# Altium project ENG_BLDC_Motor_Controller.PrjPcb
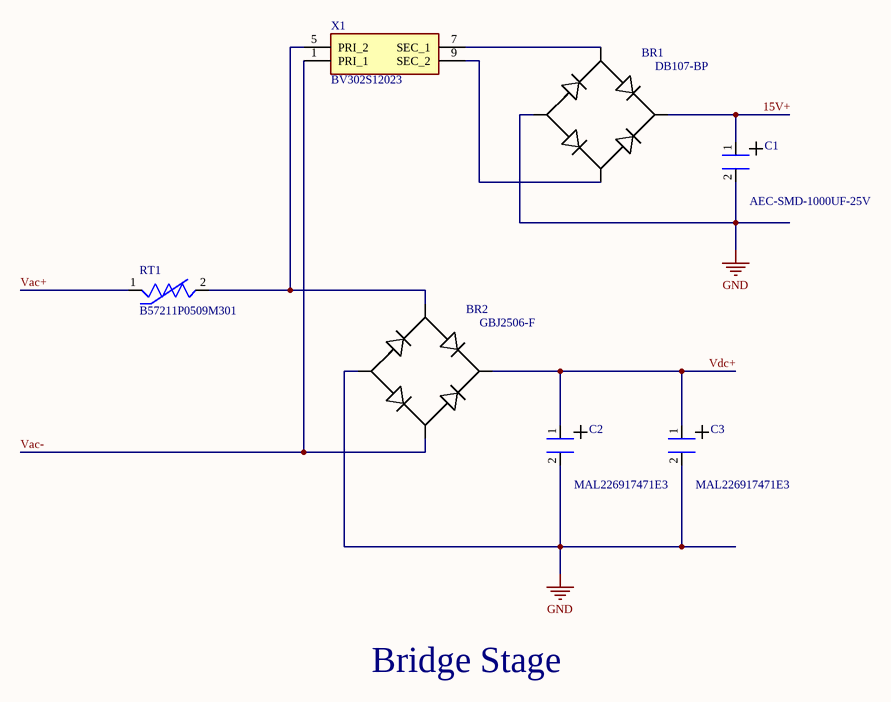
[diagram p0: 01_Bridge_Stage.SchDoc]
3 sheets, 49 parts. Net scope: global (net labels, ports and power ports of the same name join across sheets).
Board file: PCB_Main.PcbDoc
Sheets:
  01_Bridge_Stage.SchDoc
  02_MosfetDrive_Stage.SchDoc
  03_Headers-Mesaurements.SchDoc

## Sheet 01_Bridge_Stage.SchDoc
size A4; SheetNumber: 1; SheetTotal: 3

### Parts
BR1  DB107-BP  [898_DB107-BP]
BR2  GBJ2506-F  [996_GBJ2506-F]
C1  AEC-SMD-1000UF-25V  [098_AEC-SMD-1000UF-25V]
C2  MAL226917471E3  [099_MAL226917471E3]
C3  MAL226917471E3  [099_MAL226917471E3]
RT1  B57211P0509M301  [307_THRMRB750W80L1300T600H2000]
X1  BV302S12023  [899_BV302S12023]

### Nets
GND: BR1.2 BR2.4 C1.2 C2.2 C3.2
15V+: BR1.1 C1.1
Vac+: RT1.1
Vac-: BR2.3 X1.1(PRI_1)
Vdc+: BR2.1 C2.1 C3.1
NetBR1_3: BR1.3 X1.7(SEC_1)
NetBR1_4: BR1.4 X1.9(SEC_2)
NetBR2_2: BR2.2 RT1.2 X1.5(PRI_2)

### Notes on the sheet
- Bridge Stage

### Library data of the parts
BR1 = DB107-BP: Description; Manufacturer_Name: MCC
BR2 = GBJ2506-F: Bridge Rectifier; Manufacturer_Name: Diodes Incorporated
C1 = AEC-SMD-1000UF-25V: 1000 µF, 25 V polarized aluminum electrolytic capacitor, SMD V-chip package, Ø10 mm body, approx. 10.5 mm height, 105 °C rated.
C2 C3 = MAL226917471E3: 470 µF, 450 V polarized aluminum electrolytic capacitor, snap-in THT, Ø35 mm body, 10 mm lead spacing, 105 °C rated.
RT1 = B57211P0509M301: Inrush Current Limiter 5 Ohms Â±20% 5 A 0.512 (13.00mm); MF: EPCOS
X1 = BV302S12023: 2.3VA Encapsulated Transformer 50/60Hz; Manufacturer_Name: Zettler Group; Geometry.Height: 29.8mm

## Sheet 02_MosfetDrive_Stage.SchDoc
size A4; SheetNumber: 2; SheetTotal: 3
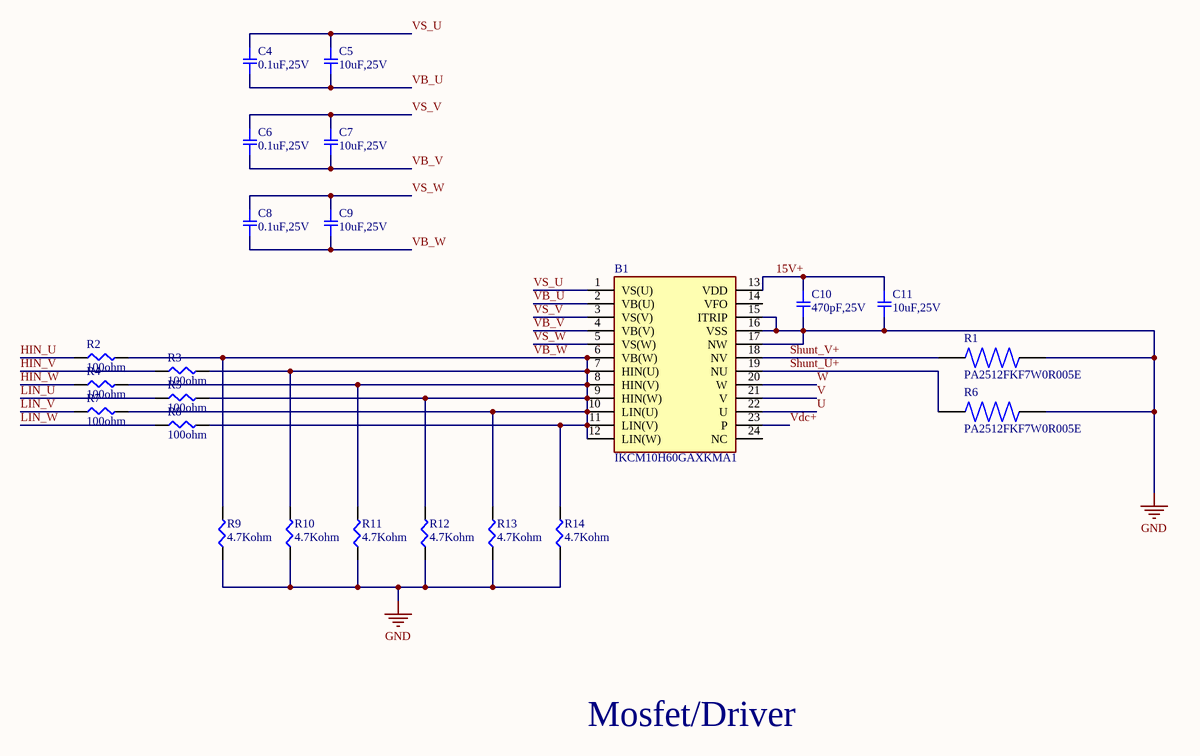
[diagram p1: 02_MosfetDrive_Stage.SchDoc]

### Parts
B1  IKCM10H60GAXKMA1  [997_IKCM10H60GAXKMA1]
C4  0.1uF,25V  [001_SMD-1206]
C5  10uF,25V  [001_SMD-1206]
C6  0.1uF,25V  [001_SMD-1206]
C7  10uF,25V  [001_SMD-1206]
C8  0.1uF,25V  [001_SMD-1206]
C9  10uF,25V  [001_SMD-1206]
C10  470pF,25V  [006_SMD_0605]
C11  10uF,25V  [006_SMD_0605]
R1  PA2512FKF7W0R005E  [097_PA2512FKF7W0R005E]
R2  100ohm  [001_SMD-1206]
R3  100ohm  [001_SMD-1206]
R4  100ohm  [001_SMD-1206]
R5  100ohm  [001_SMD-1206]
R6  PA2512FKF7W0R005E  [097_PA2512FKF7W0R005E]
R7  100ohm  [001_SMD-1206]
R8  100ohm  [001_SMD-1206]
R9  4.7Kohm  [001_SMD-1206]
R10  4.7Kohm  [001_SMD-1206]
R11  4.7Kohm  [001_SMD-1206]
R12  4.7Kohm  [001_SMD-1206]
R13  4.7Kohm  [001_SMD-1206]
R14  4.7Kohm  [001_SMD-1206]

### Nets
GND: B1.15(ITRIP) B1.16(VSS) B1.17(NW) C10.2 C11.2 R1.2 R6.2 R9.1 R10.1 R11.1 R12.1 R13.1 R14.1
15V+: B1.13(VDD) C10.1 C11.1
HIN_U: R2.1
HIN_V: R3.1
HIN_W: R4.1
LIN_U: R5.1
LIN_V: R7.1
LIN_W: R8.1
Shunt_U+: B1.19(NU) R6.1
Shunt_V+: B1.18(NV) R1.1
U: B1.22(U)
V: B1.21(V)
VB_U: B1.2(VB(U)) C4.2 C5.2
VB_V: B1.4(VB(V)) C6.2 C7.2
VB_W: B1.6(VB(W)) B1.7(HIN(U)) B1.8(HIN(V)) B1.9(HIN(W)) B1.10(LIN(U)) B1.11(LIN(V)) B1.12(LIN(W)) C8.2 C9.2 R2.2 R3.2 R4.2 R5.2 R7.2 R8.2 R9.2 R10.2 R11.2 R12.2 R13.2 R14.2
Vdc+: B1.23(P)
VS_U: B1.1(VS(U)) C4.1 C5.1
VS_V: B1.3(VS(V)) C6.1 C7.1
VS_W: B1.5(VS(W)) C8.1 C9.1
W: B1.20(W)

Not connected (* = marked no-connect by the designer): B1 14(VFO) 24(NC)

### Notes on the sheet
- Mosfet/Driver

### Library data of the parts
B1 = IKCM10H60GAXKMA1: Intelligent Power Module 3-Ph 600V 10A; Manufacturer_Name: Infineon; Geometry.Height: 5.6mm
C4-C9 = C_1206_Template: CAP CER 1206; Part Number: GC321AD72E103KX01D; Manufacturer: Murata Electronics North America; Factory Stock: 0; Unit Price (USD): 0.3; Minimum Quantity: 1; Value: 10000pF; Tolerance: ±10%; Voltage: 250V; Temperature Coefficient: X7T
C10 C11 = C_0605_Template: CAP CER 0605; Part Number: GC321AD72E103KX01D; Manufacturer: Murata Electronics North America; Factory Stock: 0; Unit Price (USD): 0.3; Minimum Quantity: 1; Value: 10000pF; Tolerance: ±10%; Voltage: 250V; Temperature Coefficient: X7T
R1 R6 = PA2512FKF7W0R005E: 5 mΩ, 2 W, ±1% current-sense shunt resistor, 2512 (6332 metric) SMD package, low-resistance metal-element construction.; MF: Bourns; MP: CRF2512-FZ-R005ELF
R2-R5 R7-R14 = R_1206_Template: RES SMD 1206; Part Number: ERJ-8BQF1R0V; Manufacturer: Panasonic Electronic Components; Factory Stock: 0; Unit Price (USD): 0.05778; @ qty: 1500; Minimum Quantity: 1; Value: 1; Tolerance: ±1%; Power (Watts): 0.5W, 1/2W; Temperature Coefficient: ±200ppm/°C

## Sheet 03_Headers-Mesaurements.SchDoc
size A4; SheetNumber: 3; SheetTotal: 3
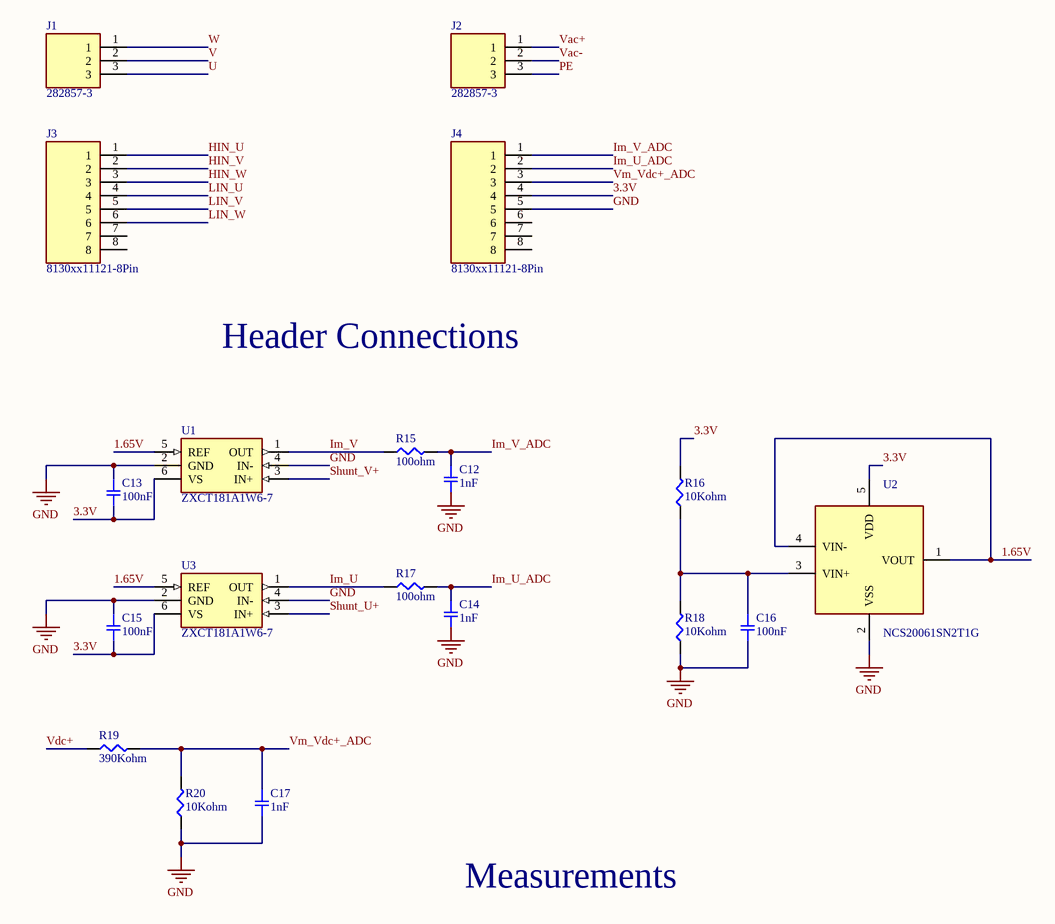
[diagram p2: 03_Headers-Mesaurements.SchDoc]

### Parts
C12  1nF  [006_SMD_0605]
C13  100nF  [006_SMD_0605]
C14  1nF  [006_SMD_0605]
C15  100nF  [006_SMD_0605]
C16  100nF  [001_SMD-1206]
C17  1nF  [006_SMD_0605]
J1  282857-3  [201_TE_282857-3]
J2  282857-3  [201_TE_282857-3]
J3  8130xx11121-8Pin  [200_HDRV6W64P0X254_1X6_1524X254X869P]
J4  8130xx11121-8Pin  [200_HDRV6W64P0X254_1X6_1524X254X869P]
R15  100ohm  [006_SMD_0605]
R16  10Kohm  [001_SMD-1206]
R17  100ohm  [006_SMD_0605]
R18  10Kohm  [001_SMD-1206]
R19  390Kohm  [001_SMD-1206]
R20  10Kohm  [001_SMD-1206]
U1  ZXCT181A1W6-7  [896_ZXCT181A1W6-7]
U2  NCS20061SN2T1G  [897_NCS20061SN2T1G]
U3  ZXCT181A1W6-7  [896_ZXCT181A1W6-7]

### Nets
GND: C12.2 C13.1 C14.2 C15.1 C16.2 C17.2 J4.5 R18.1 R20.1 U1.2(GND) U1.4(IN-) U2.2(VSS) U3.2(GND) U3.4(IN-)
1.65V: U1.5(REF) U2.1(VOUT) U2.4(VIN-) U3.5(REF)
3.3V: C13.2 C15.2 J4.4 R16.2 U1.6(VS) U2.5(VDD) U3.6(VS)
HIN_U: J3.1
HIN_V: J3.2
HIN_W: J3.3
Im_U: R17.1 U3.1(OUT)
Im_U_ADC: C14.1 J4.2 R17.2
Im_V: R15.1 U1.1(OUT)
Im_V_ADC: C12.1 J4.1 R15.2
LIN_U: J3.4
LIN_V: J3.5
LIN_W: J3.6
PE: J2.3
Shunt_U+: U3.3(IN+)
Shunt_V+: U1.3(IN+)
U: J1.3
V: J1.2
Vac+: J2.1
Vac-: J2.2
Vdc+: R19.1
Vm_Vdc+_ADC: C17.1 J4.3 R19.2 R20.2
W: J1.1
NetC16_1: C16.1 R16.1 R18.2 U2.3(VIN+)

Not connected (* = marked no-connect by the designer): J3 7 8; J4 6 7 8

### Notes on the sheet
- Header Connections
- Measurements

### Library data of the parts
C12-C15 C17 = C_0605_Template: as C10 on sheet 02_MosfetDrive_Stage
C16 = C_1206_Template: as C4 on sheet 02_MosfetDrive_Stage
J1 J2 = 282857-3: 3 Position Wire to Board Terminal Block Horizontal with Board 0.200 (5.08mm) Through Hole; MF: TE Connectivity
J3 J4 = 6130xx11121-6Pin: 2.54MM PIN HEADER; Manufacturer_Name: Wurth Elektronik; Geometry.Height: 8.69mm
R15 R17 = R_0605_Template: RES SMD 0605; Part Number: ERJ-6BQF1R0V; Manufacturer: Panasonic Electronic Components; Factory Stock: 0; Unit Price (USD): 0.05834; @ qty: 1500; Minimum Quantity: 1; Value: 1; Tolerance: ±1%; Power (Watts): 0.333W, 1/3W; Temperature Coefficient: ±200ppm/°C
R16 R18-R20 = R_1206_Template: as R2 on sheet 02_MosfetDrive_Stage
U1 U3 = ZXCT181A1W6-7: Bidirectional high-side current-sense amplifier, fixed gain 20 V/V, 2.7–5.5 V supply, up to 26 V common-mode input range, SOT-26 package.; MF: Texas Instruments; MP: INA181A1IDBVR
U2 = NCS20061SN2T1G: Single, rail-to-rail operational amplifier used as a voltage buffer for the 1.65 V current-sense reference.

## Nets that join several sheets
GND: 01_Bridge_Stage (5 pins), 02_MosfetDrive_Stage (13 pins), 03_Headers-Mesaurements (14 pins)
15V+: 01_Bridge_Stage (BR1.1 C1.1), 02_MosfetDrive_Stage (B1.13 C10.1 C11.1)
HIN_U: 02_MosfetDrive_Stage (R2.1), 03_Headers-Mesaurements (J3.1)
HIN_V: 02_MosfetDrive_Stage (R3.1), 03_Headers-Mesaurements (J3.2)
HIN_W: 02_MosfetDrive_Stage (R4.1), 03_Headers-Mesaurements (J3.3)
LIN_U: 02_MosfetDrive_Stage (R5.1), 03_Headers-Mesaurements (J3.4)
LIN_V: 02_MosfetDrive_Stage (R7.1), 03_Headers-Mesaurements (J3.5)
LIN_W: 02_MosfetDrive_Stage (R8.1), 03_Headers-Mesaurements (J3.6)
Shunt_U+: 02_MosfetDrive_Stage (B1.19 R6.1), 03_Headers-Mesaurements (U3.3)
Shunt_V+: 02_MosfetDrive_Stage (B1.18 R1.1), 03_Headers-Mesaurements (U1.3)
U: 02_MosfetDrive_Stage (B1.22), 03_Headers-Mesaurements (J1.3)
V: 02_MosfetDrive_Stage (B1.21), 03_Headers-Mesaurements (J1.2)
Vac+: 01_Bridge_Stage (RT1.1), 03_Headers-Mesaurements (J2.1)
Vac-: 01_Bridge_Stage (BR2.3 X1.1), 03_Headers-Mesaurements (J2.2)
Vdc+: 01_Bridge_Stage (BR2.1 C2.1 C3.1), 02_MosfetDrive_Stage (B1.23), 03_Headers-Mesaurements (R19.1)
W: 02_MosfetDrive_Stage (B1.20), 03_Headers-Mesaurements (J1.1)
